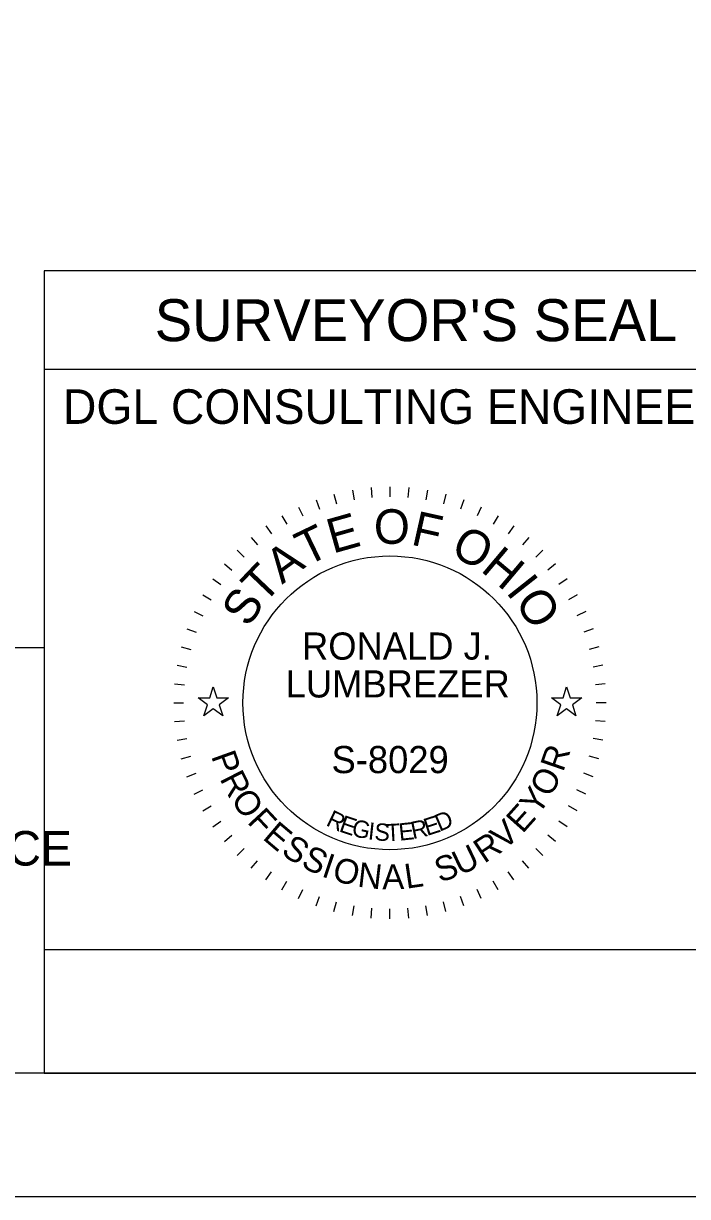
# Model space of a CAD drawing. Extents: x 0 to 34, y -0.2 to 22.
# Drawn here: x 29.117 to 31.804, y 0 to 4.752 of the extents above; entities that cross this region are included whole.
import ezdxf

# ---------------------------------------------------------------- set-up
doc = ezdxf.new("R2010")
doc.units = 0
for name, color, linetype in [('Default', 7, 'Continuous'), ('SH_Border', 7, 'Continuous'), ('SH_Cut_Line', 7, 'Continuous'), ('SH_Data', 7, 'Continuous'), ('SH_Text', 7, 'Continuous')]:
    doc.layers.add(name, color=color, linetype=linetype)

msp = doc.modelspace()

# ---------------------------------------------------------------- linework, layer by layer
at = {"layer": 'Default'}
for points in [[(29.8236, 2.02), (29.8705, 2.02), (29.885, 2.0645), (29.8995, 2.02), (29.9464, 2.02), (29.9085, 1.9924), (29.923, 1.9478), (29.885, 1.9754), (29.847, 1.9478), (29.8615, 1.9924)], [(31.2536, 2.02), (31.3005, 2.02), (31.315, 2.0645), (31.3295, 2.02), (31.3764, 2.02), (31.3385, 1.9924), (31.353, 1.9478), (31.315, 1.9754), (31.277, 1.9478), (31.2915, 1.9924)]]:
    msp.add_lwpolyline(points, close=True, dxfattribs=at)
at = {"layer": 'SH_Border'}
msp.add_lwpolyline([(1.5, 21.5), (33.5, 21.5), (33.5, 0.5), (1.5, 0.5)], close=True, dxfattribs=at)
at = {"layer": 'SH_Cut_Line'}
msp.add_lwpolyline([(0, 0), (34, 0), (34, 22), (0, 22)], close=True, dxfattribs=at)
at = {"layer": 'SH_Data'}
for p, q in [((32, 3.75), (29.2, 3.75)), ((29.2, 3.75), (29.2, 0.5)), ((32, 3.35), (29.2, 3.35)), ((30.4481, 2.8617), (30.455, 2.8223)), ((30.5237, 2.8717), (30.5272, 2.8318)), ((30.6, 2.875), (30.6, 2.835)), ((30.6763, 2.8717), (30.6728, 2.8318)), ((30.7519, 2.8617), (30.745, 2.8223)), ((30.3007, 2.8222), (30.3144, 2.7846)), ((30.3735, 2.8452), (30.3839, 2.8065)), ((30.8265, 2.8452), (30.8161, 2.8065)), ((30.8993, 2.8222), (30.8856, 2.7846)), ((30.1625, 2.7578), (30.1825, 2.7231)), ((30.2302, 2.793), (30.2471, 2.7568)), ((30.9698, 2.793), (30.9529, 2.7568)), ((31.0375, 2.7578), (31.0175, 2.7231)), ((30.0981, 2.7168), (30.1211, 2.684)), ((31.1019, 2.7168), (31.0789, 2.684)), ((30.0376, 2.6703), (30.0633, 2.6396)), ((31.1624, 2.6703), (31.1367, 2.6396)), ((29.9813, 2.6187), (30.0096, 2.5904)), ((31.2187, 2.6187), (31.1904, 2.5904)), ((29.9297, 2.5624), (29.9604, 2.5367)), ((31.2703, 2.5624), (31.2396, 2.5367)), ((29.8832, 2.5019), (29.916, 2.4789)), ((31.3168, 2.5019), (31.284, 2.4789)), ((29.8422, 2.4375), (29.8769, 2.4175)), ((31.3578, 2.4375), (31.3231, 2.4175)), ((29.807, 2.3698), (29.8432, 2.3529)), ((31.393, 2.3698), (31.3568, 2.3529)), ((29.7778, 2.2993), (29.8154, 2.2856)), ((31.4222, 2.2993), (31.3846, 2.2856)), ((29.7548, 2.2265), (29.7935, 2.2161)), ((31.4452, 2.2265), (31.4065, 2.2161)), ((29.7383, 2.1519), (29.7777, 2.145)), ((31.4617, 2.1519), (31.4223, 2.145)), ((29.7283, 2.0763), (29.7682, 2.0728)), ((31.4717, 2.0763), (31.4318, 2.0728)), ((29.725, 2), (29.765, 2)), ((31.475, 2), (31.435, 2)), ((29.7283, 1.9237), (29.7682, 1.9272)), ((31.4717, 1.9237), (31.4318, 1.9272)), ((29.7383, 1.8481), (29.7777, 1.855)), ((31.4617, 1.8481), (31.4223, 1.855)), ((29.7548, 1.7735), (29.7935, 1.7839)), ((31.4452, 1.7735), (31.4065, 1.7839)), ((29.7778, 1.7007), (29.8154, 1.7144)), ((31.4222, 1.7007), (31.3846, 1.7144)), ((29.807, 1.6302), (29.8432, 1.6471)), ((31.393, 1.6302), (31.3568, 1.6471)), ((29.8422, 1.5625), (29.8769, 1.5825)), ((31.3578, 1.5625), (31.3231, 1.5825)), ((29.8832, 1.4981), (29.916, 1.5211)), ((31.3168, 1.4981), (31.284, 1.5211)), ((29.9297, 1.4376), (29.9604, 1.4633)), ((31.2703, 1.4376), (31.2396, 1.4633)), ((29.9813, 1.3813), (30.0096, 1.4096)), ((31.2187, 1.3813), (31.1904, 1.4096)), ((30.0376, 1.3297), (30.0633, 1.3604)), ((31.1624, 1.3297), (31.1367, 1.3604)), ((30.0981, 1.2832), (30.1211, 1.316)), ((31.1019, 1.2832), (31.0789, 1.316)), ((30.1625, 1.2422), (30.1825, 1.2769)), ((30.2302, 1.207), (30.2471, 1.2432)), ((30.9698, 1.207), (30.9529, 1.2432)), ((31.0375, 1.2422), (31.0175, 1.2769)), ((30.3007, 1.1778), (30.3144, 1.2154)), ((30.3735, 1.1548), (30.3839, 1.1935)), ((30.8265, 1.1548), (30.8161, 1.1935)), ((30.8993, 1.1778), (30.8856, 1.2154)), ((30.4481, 1.1383), (30.455, 1.1777)), ((30.5237, 1.1283), (30.5272, 1.1682)), ((30.6, 1.125), (30.6, 1.165)), ((30.6763, 1.1283), (30.6728, 1.1682)), ((30.7519, 1.1383), (30.745, 1.1777)), ((32, 0.5), (29.2, 0.5))]:
    msp.add_line(p, q, dxfattribs=at)
msp.add_lwpolyline([(32, 0.5), (32, 1), (29.2, 1), (29.2, 0.5)], close=True, dxfattribs=at)
msp.add_circle((30.6, 2), 0.595, dxfattribs=at)
at = {"layer": 'SH_Text'}
for p, q in [((25.8238, 2.2242), (29.2, 2.2242)), ((29.2, 2.2242), (29.2, 0.5))]:
    msp.add_line(p, q, dxfattribs=at)

# ---------------------------------------------------------------- texts
at = {"layer": 'SH_Data'}
for s, height, p in [("SURVEYOR'S SEAL", 0.17, (29.6478, 3.465)), ('DGL CONSULTING ENGINEERS', 0.14, (29.2766, 3.13)), ('RONALD J.', 0.11, (30.2441, 2.1749)), ('LUMBREZER', 0.11, (30.1779, 2.0216)), ('S-8029', 0.11, (30.3636, 1.7151))]:
    msp.add_text(s, height=height, dxfattribs=at).set_placement(p)
for s, height, rotation, p in [('E', 0.14, 15.7571, (30.3684, 2.6038)), ('O', 0.14, 359.7812, (30.5347, 2.6443)), ('F', 0.14, 347.4362, (30.6811, 2.6417)), ('T', 0.14, 25.7167, (30.2616, 2.5518)), ('O', 0.14, 332.2586, (30.8398, 2.6015)), ('A', 0.14, 36.4747, (30.1634, 2.4781)), ('H', 0.14, 319.9136, (30.9632, 2.5361)), ('T', 0.14, 46.4344, (30.0883, 2.3964)), ('I', 0.14, 308.367, (31.0665, 2.4483)), ('S', 0.14, 57.1924, (30.0281, 2.3014)), ('O', 0.14, 303.1491, (31.1021, 2.4089)), ('P', 0.1, 289.7431, (29.8753, 1.7841)), ('R', 0.1, 70.983, (31.3009, 1.7167)), ('R', 0.1, 296.9802, (29.9093, 1.6927)), ('O', 0.1, 62.7428, (31.2501, 1.6133)), ('Y', 0.1, 55.5058, (31.2, 1.54)), ('O', 0.1, 304.7158, (29.9532, 1.6079)), ('F', 0.1, 312.956, (30.0192, 1.5158)), ('E', 0.1, 48.2687, (31.1366, 1.4673)), ('R', 0.07, 334.487, (30.3375, 1.5051)), ('E', 0.07, 341.04, (30.3906, 1.4801)), ('G', 0.07, 347.4752, (30.4414, 1.4618)), ('R', 0.07, 11.9184, (30.6925, 1.4474)), ('E', 0.07, 17.6836, (30.7498, 1.4602)), ('D', 0.07, 23.3052, (30.801, 1.477)), ('V', 0.1, 41.0316, (31.0615, 1.4007)), ('E', 0.1, 319.6885, (30.0808, 1.4504)), ('I', 0.07, 353.7858, (30.5091, 1.4468)), ('S', 0.07, 356.8926, (30.5358, 1.4429)), ('T', 0.07, 3.0061, (30.5857, 1.4387)), ('E', 0.07, 6.0117, (30.6389, 1.4412)), ('S', 0.1, 326.9255, (30.1554, 1.3885)), ('U', 0.1, 25.5604, (30.8833, 1.2986)), ('R', 0.1, 33.296, (30.9815, 1.3473)), ('S', 0.1, 334.1626, (30.236, 1.3374)), ('I', 0.1, 341.3997, (30.3191, 1.2979)), ('S', 0.1, 18.3234, (30.8005, 1.2711)), ('O', 0.1, 345.1351, (30.3618, 1.2821)), ('N', 0.1, 353.3752, (30.466, 1.2555)), ('A', 0.1, 1.1108, (30.5692, 1.2443)), ('L', 0.1, 8.3479, (30.6664, 1.2467))]:
    msp.add_text(s, height=height, rotation=rotation, dxfattribs=at).set_placement(p)
at = {"layer": 'SH_Text'}
msp.add_text("WOOD COUNTY RECORDER'S OFFICE", height=0.14, dxfattribs=at).set_placement((25.8444, 1.3406))

doc.saveas('drawing.dxf')
